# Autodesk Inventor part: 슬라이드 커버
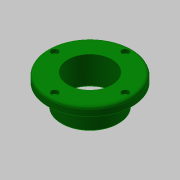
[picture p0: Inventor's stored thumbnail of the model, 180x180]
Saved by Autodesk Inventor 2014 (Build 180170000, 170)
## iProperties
Created: 2015-10
Part Number: 슬라이드 커버
Document SubType Name: Modeling
Designer: mdu
Density: 2.71 g/cm^3
Material: 알루미늄 6061
Mass: 218.252 g
Surface Area: 239.629 cm^2
Volume: 80.5358 cm^3
Appearance: 진녹색
Author: mdu
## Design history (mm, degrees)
sketch "스케치1"
  geometry: C1 r 47.5 at (0, 0); C2 r 32.5 at (0, 0); 1 further point
  constraints: 2 centre point, 2 coincident
  dimensions: "d33" = 95 diameter of C1; "d35" = 65 diameter of C2
extrude "돌출1" new body sketch "스케치1" distance "d0" = 10; taper "d1" = 0 deg
extrude "돌출2" join sketch "스케치1" distance "d2" = 25; taper "d3" = 0 deg
hole "구멍1" diameter "d6" = 50; stored, may be unused: countersink angle "d10" = 90 deg, drill point angle "d12" = 118 deg; dims "d4" = 10, "d5" = 10, "d7" = 6, "d8" = 4, "d9" = 2, "d11" = 8
sketch "스케치2" dims "d36" = 80
  geometry: 4 further points
  constraints: 2 coincident, 2 vertical alignment, 2 other
hole "구멍2" sketch "스케치2" at (0, 40) diameter "d13" = 4.5; stored, may be unused: countersink angle "d17" = 90 deg, drill point angle "d19" = 118 deg; dims "d14" = 6, "d15" = 8, "d16" = 4.4, "d18" = 8
fillet "모깎기1" dims "d23" = 3
chamfer "모따기1" distance "d24" = 1; stored, may be unused: second distance "d25" = 2, angle "d26" = 45 deg
sketch "스케치3"
  geometry: C1 r 25 at (0, 0); C2 r 30 at (0, 0); C3 r 26 at (0, 0) reference; 1 further point
  constraints: 2 centre point, 2 coincident
  dimensions: "d27" = 60 diameter of C2
extrude "돌출3" cut sketch "스케치3" distance "d28" = 3; taper "d29" = 0 deg
chamfer "모따기2" distance "d30" = 1; stored, may be unused: second distance "d31" = 2, angle "d32" = 45 deg
node "솔리드1"
pattern_circular "원형 패턴1" dims angle "d21" = 360 deg
